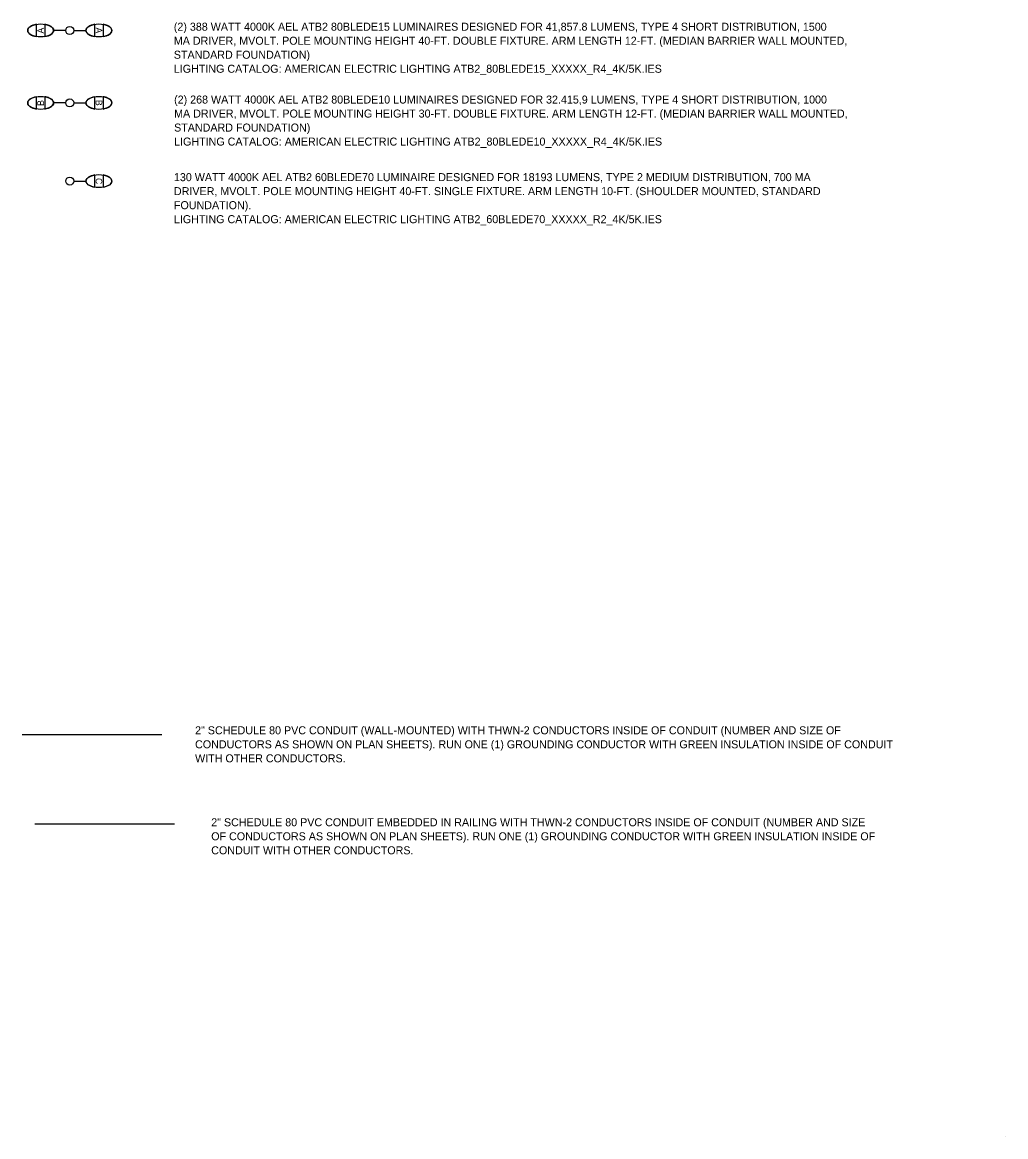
# Model space of a CAD drawing. Extents: x -9.1 to 15.2, y -0.9 to 9.2.
# Drawn here: x -9.15 to -0.55, y -0.9 to 8.84 of the extents above; entities that cross this region are included whole.
import ezdxf

# ---------------------------------------------------------------- set-up
doc = ezdxf.new("R2010")
doc.units = 0
for name, color, linetype in [('AdhocPoint_dp', 7, 'Continuous'), ('Miscellaneous7', 7, 'Continuous'), ('Miscellaneous8', 7, 'Continuous'), ('PoleLight', 7, 'Continuous'), ('TextLabel', 7, 'Continuous'), ('TextMisc', 7, 'Continuous')]:
    doc.layers.add(name, color=color, linetype=linetype)

msp = doc.modelspace()

# ---------------------------------------------------------------- linework, layer by layer
at = {"layer": 'AdhocPoint_dp'}
msp.add_line((-0.55, -0.9), (-0.55, -0.9), dxfattribs=at)
at = {"layer": 'Miscellaneous7'}
msp.add_line((-9.0358, 1.8362), (-7.8153, 1.8362), dxfattribs=at)
at = {"layer": 'Miscellaneous8'}
msp.add_line((-9.1463, 2.6182), (-7.9259, 2.6182), dxfattribs=at)
at = {"layer": 'PoleLight'}
for p, q in [((-9.0217, 8.719), (-9.0217, 8.8264)), ((-8.9502, 8.8264), (-8.9502, 8.719)), ((-8.7665, 8.7727), (-8.8727, 8.7727)), ((-8.6957, 8.7727), (-8.5895, 8.7727)), ((-8.512, 8.719), (-8.512, 8.8264)), ((-8.4405, 8.8264), (-8.4405, 8.719)), ((-9.0217, 8.0857), (-9.0217, 8.1932)), ((-8.9502, 8.1932), (-8.9502, 8.0857)), ((-8.512, 8.0857), (-8.512, 8.1932)), ((-8.4405, 8.1932), (-8.4405, 8.0857)), ((-8.7665, 8.1394), (-8.8727, 8.1394)), ((-8.6957, 8.1394), (-8.5895, 8.1394)), ((-8.512, 7.402), (-8.512, 7.5095)), ((-8.4405, 7.5095), (-8.4405, 7.402)), ((-8.6957, 7.4558), (-8.5895, 7.4558))]:
    msp.add_line(p, q, dxfattribs=at)
for centre in [(-8.7311, 8.7727), (-8.7311, 8.7727), (-8.7311, 8.1394), (-8.7311, 8.1394), (-8.7311, 7.4558), (-8.7311, 7.4558)]:
    msp.add_circle(centre, 0.0354, dxfattribs=at)
for centre in [(-8.9859, 8.7727), (-8.4763, 8.7727), (-8.9859, 8.1394), (-8.4763, 8.1394), (-8.4763, 7.4558)]:
    msp.add_ellipse(centre, major_axis=(0.1133, 0), ratio=0.5, dxfattribs=at)
for centre, start_param, end_param in [((-8.9859, 8.7727), 1.891945, 4.391241), ((-8.9859, 8.7727), 0.847605, 1.249648), ((-8.9859, 8.7727), 5.033538, 6.283185), ((-8.9859, 8.7727), 0, 0.847605), ((-8.4763, 8.7727), 1.891945, 4.391241), ((-8.4763, 8.7727), 0.847605, 1.249648), ((-8.4763, 8.7727), 5.033538, 6.283185), ((-8.4763, 8.7727), 0, 0.847605), ((-8.9859, 8.1394), 1.891945, 4.391241), ((-8.9859, 8.1394), 0.847605, 1.249648), ((-8.4763, 8.1394), 1.891945, 4.391241), ((-8.4763, 8.1394), 0.847605, 1.249648), ((-8.9859, 8.1394), 5.033538, 6.283185), ((-8.9859, 8.1394), 0, 0.847605), ((-8.4763, 8.1394), 5.033538, 6.283185), ((-8.4763, 8.1394), 0, 0.847605), ((-8.4763, 7.4558), 1.891945, 4.391241), ((-8.4763, 7.4558), 0.847605, 1.249648), ((-8.4763, 7.4558), 5.033538, 6.283185), ((-8.4763, 7.4558), 0, 0.847605)]:
    msp.add_ellipse(centre, major_axis=(0.1133, 0), ratio=0.5, start_param=start_param, end_param=end_param, dxfattribs=at)

# ---------------------------------------------------------------- texts
at = {"layer": 'TextLabel'}
for s, rotation, p in [('A', 90, (-8.9573, 8.746)), ('A', 270, (-8.5049, 8.7993)), ('B', 90, (-8.9573, 8.1133)), ('B', 270, (-8.5049, 8.1656)), ('C', 270, (-8.5049, 7.4825))]:
    msp.add_text(s, height=0.0572, rotation=rotation, dxfattribs=at).set_placement(p)
at = {"layer": 'TextMisc'}
for s, p in [('(2) 388 WATT 4000K AEL ATB2 80BLEDE15 LUMINAIRES DESIGNED FOR 41,857.8 LUMENS, TYPE 4 SHORT DISTRIBUTION, 1500 ', (-7.8218, 8.7706)), ('MA DRIVER, MVOLT. POLE MOUNTING HEIGHT 40-FT. DOUBLE FIXTURE. ARM LENGTH 12-FT. (MEDIAN BARRIER WALL MOUNTED, ', (-7.8218, 8.6481)), ('STANDARD FOUNDATION)', (-7.8218, 8.5256)), ('LIGHTING CATALOG: AMERICAN ELECTRIC LIGHTING ATB2_80BLEDE15_XXXXX_R4_4K/5K.IES', (-7.8218, 8.4031)), ('(2) 268 WATT 4000K AEL ATB2 80BLEDE10 LUMINAIRES DESIGNED FOR 32.415,9 LUMENS, TYPE 4 SHORT DISTRIBUTION, 1000 ', (-7.8193, 8.1337)), ('MA DRIVER, MVOLT. POLE MOUNTING HEIGHT 30-FT. DOUBLE FIXTURE. ARM LENGTH 12-FT. (MEDIAN BARRIER WALL MOUNTED, ', (-7.8193, 8.0112)), ('STANDARD FOUNDATION)', (-7.8193, 7.8887)), ('LIGHTING CATALOG: AMERICAN ELECTRIC LIGHTING ATB2_80BLEDE10_XXXXX_R4_4K/5K.IES', (-7.8193, 7.7662)), ('130 WATT 4000K AEL ATB2 60BLEDE70 LUMINAIRE DESIGNED FOR 18193 LUMENS, TYPE 2 MEDIUM DISTRIBUTION, 700 MA ', (-7.8207, 7.4552)), ('DRIVER, MVOLT. POLE MOUNTING HEIGHT 40-FT. SINGLE FIXTURE. ARM LENGTH 10-FT. (SHOULDER MOUNTED, STANDARD ', (-7.8207, 7.3327)), ('FOUNDATION). ', (-7.8207, 7.2102)), ('LIGHTING CATALOG: AMERICAN ELECTRIC LIGHTING ATB2_60BLEDE70_XXXXX_R2_4K/5K.IES', (-7.8207, 7.0877))]:
    msp.add_text(s, height=0.07, dxfattribs=at).set_placement(p)
for s, p in [('2" SCHEDULE 80 PVC CONDUIT (WALL-MOUNTED) WITH THWN-2 CONDUCTORS INSIDE OF CONDUIT (NUMBER AND SIZE OF ', (-7.6359, 2.6186)), ('CONDUCTORS AS SHOWN ON PLAN SHEETS). RUN ONE (1) GROUNDING CONDUCTOR WITH GREEN INSULATION INSIDE OF CONDUIT ', (-7.6359, 2.4961)), ('WITH OTHER CONDUCTORS.', (-7.6359, 2.3736)), ('2" SCHEDULE 80 PVC CONDUIT EMBEDDED IN RAILING WITH THWN-2 CONDUCTORS INSIDE OF CONDUIT (NUMBER AND SIZE ', (-7.4949, 1.8143)), ('OF CONDUCTORS AS SHOWN ON PLAN SHEETS). RUN ONE (1) GROUNDING CONDUCTOR WITH GREEN INSULATION INSIDE OF ', (-7.4949, 1.6918)), ('CONDUIT WITH OTHER CONDUCTORS.', (-7.4949, 1.5693))]:
    msp.add_text(s, height=0.07, rotation=360, dxfattribs=at).set_placement(p)

doc.saveas('drawing.dxf')
